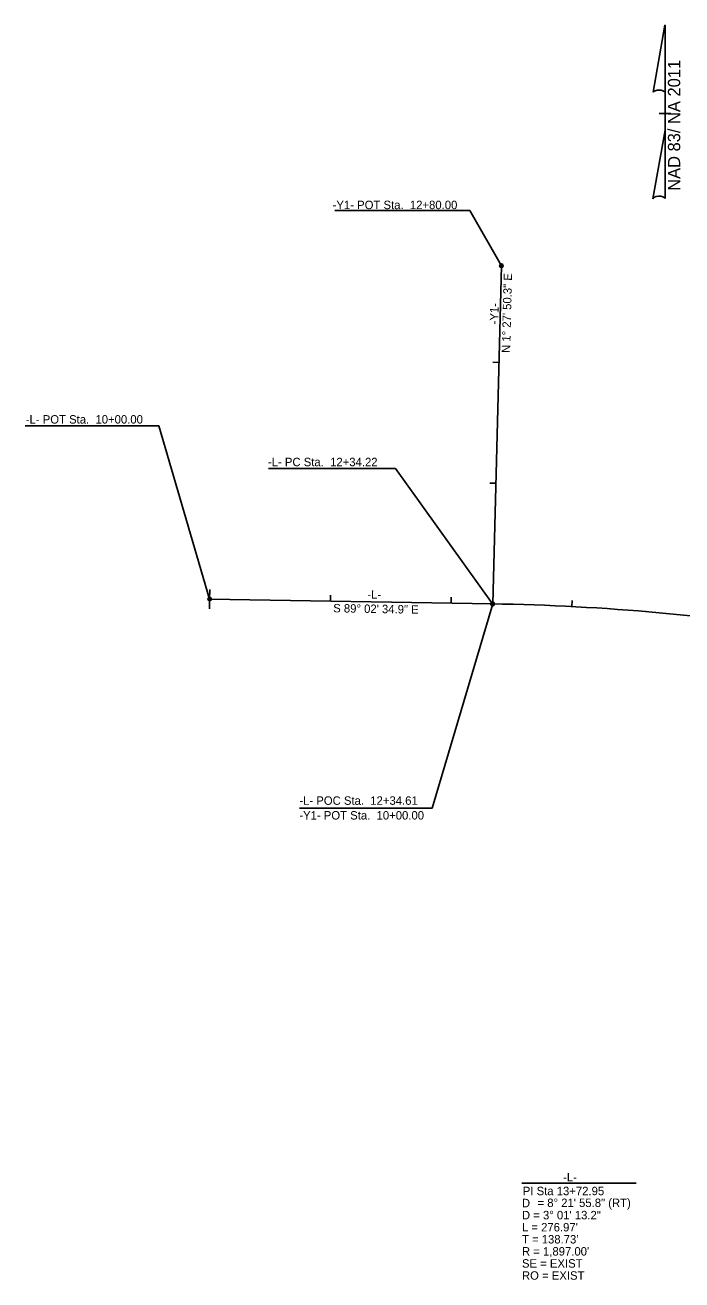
# Model space of a CAD drawing. Extents: x 1755545 to 1761252, y 736169 to 737766.
# Drawn here: x 1755545 to 1756089, y 736596 to 737635 of the extents above; entities that cross this region are included whole.
import ezdxf

# ---------------------------------------------------------------- set-up
doc = ezdxf.new("R2010")
doc.units = 0
for name, color, linetype in [('Prop Horizontal Alignment', 7, 'Continuous'), ('Prop Horizontal Alignment Curve and Spiral Data', 7, 'Continuous'), ('Prop Horizontal Alignment Direction Label', 7, 'Continuous'), ('Prop Horizontal Alignment Station Label', 7, 'Continuous'), ('Prop Horizontal Alignment Tick Large', 7, 'Continuous'), ('Prop Horizontal Alignment Tick Small', 7, 'Continuous'), ('Prop North Arrow NAD83 for Plan Sheets CELL', 7, 'Continuous')]:
    doc.layers.add(name, color=color, linetype=linetype)

msp = doc.modelspace()

# ---------------------------------------------------------------- linework, layer by layer
at = {"layer": 'Prop Horizontal Alignment'}
for p, q in [((1755932.6, 737155.4), (1755939.7, 737435.4)), ((1755698, 737159.4), (1755932.2, 737155.5))]:
    msp.add_line(p, q, dxfattribs=at)
msp.add_arc((1755900.5, 735258.7), 1897, 80.6775, 89.043, dxfattribs=at)
at = {"layer": 'Prop Horizontal Alignment Curve and Spiral Data'}
msp.add_line((1755956.5, 736675.7), (1756051.4, 736675.7), dxfattribs=at)
at = {"layer": 'Prop Horizontal Alignment Station Label'}
for p, q in [((1755801.6, 737481.2), (1755913.5, 737481.2)), ((1755939.7, 737435.4), (1755913.5, 737481.2)), ((1755545.1, 737302.8), (1755655.8, 737302.8)), ((1755698, 737159.4), (1755655.8, 737302.8)), ((1755746.8, 737267.5), (1755851.9, 737267.5)), ((1755932.2, 737155.5), (1755851.9, 737267.5)), ((1755932.6, 737155.4), (1755882.4, 736986.1)), ((1755772.3, 736986.1), (1755882.4, 736986.1))]:
    msp.add_line(p, q, dxfattribs=at)
for centre in [(1755939.7, 737435.4), (1755698, 737159.4), (1755932.2, 737155.5), (1755932.6, 737155.4)]:
    msp.add_circle(centre, 1.5, dxfattribs=at)
at = {"layer": 'Prop Horizontal Alignment Tick Large'}
for p, q in [((1755698, 737159.4), (1755698.1, 737167.4)), ((1755698, 737159.4), (1755697.8, 737151.4)), ((1755932.6, 737155.4), (1755924.6, 737155.7)), ((1755932.6, 737155.4), (1755940.6, 737155.2))]:
    msp.add_line(p, q, dxfattribs=at)
at = {"layer": 'Prop Horizontal Alignment Tick Small'}
for p, q in [((1755937.7, 737355.4), (1755932.7, 737355.5)), ((1755935.1, 737255.4), (1755930.1, 737255.5)), ((1755798, 737157.7), (1755798, 737162.7)), ((1755898, 737156), (1755898, 737161)), ((1755997.9, 737153.2), (1755998.2, 737158.2))]:
    msp.add_line(p, q, dxfattribs=at)
at = {"layer": 'Prop North Arrow NAD83 for Plan Sheets CELL'}
for p, q in [((1756065.3, 737579.1), (1756075.1, 737634.7)), ((1756075.2, 737634.7), (1756075.1, 737634.7)), ((1756075.2, 737634.7), (1756075.1, 737634.7)), ((1756075.2, 737634.7), (1756075.2, 737577.4)), ((1756075.2, 737547.6), (1756075.2, 737579)), ((1756075.2, 737577.4), (1756075.2, 737579)), ((1756070.4, 737561.5), (1756070.3, 737561.5)), ((1756074.7, 737561.5), (1756070.4, 737561.5)), ((1756070.5, 737561.5), (1756080.1, 737561.5)), ((1756075.2, 737547.6), (1756065.2, 737490.9)), ((1756075.3, 737491.1), (1756075.2, 737547.6))]:
    msp.add_line(p, q, dxfattribs=at)
for centre, start_param, end_param in [((1756070.3, 737578.5), 0.216388, 2.908219), ((1756070.3, 737490.7), 0.201328, 3.141593)]:
    msp.add_ellipse(centre, major_axis=(5.08, -0.04), ratio=0.461098, start_param=start_param, end_param=end_param, dxfattribs=at)

# ---------------------------------------------------------------- texts
at = {"layer": 'Prop Horizontal Alignment Curve and Spiral Data'}
for s, p in [('-L-', (1755990.8, 736677.2)), ('PI Sta 13+72.95', (1755957.4, 736665.7)), ('D', (1755956.7, 736655.7)), ('= 8%%d 21\' 55.8" (RT)', (1755969.6, 736655.9)), ('D = 3%%d 01\' 13.2"', (1755956.7, 736645.7)), ("L = 276.97'", (1755956.7, 736635.7)), ("T = 138.73'", (1755956.7, 736625.7)), ("R = 1,897.00'", (1755956.7, 736615.7)), ('SE = EXIST', (1755956.7, 736605.7)), ('RO = EXIST', (1755956.7, 736595.7))]:
    msp.add_text(s, height=7, dxfattribs=at).set_placement(p)
at = {"layer": 'Prop Horizontal Alignment Direction Label'}
for s, rotation, p in [('N 1%%d 27\' 50.3" E', 88.536, (1755946.9, 737363.1)), ('-Y1-', 88.536, (1755937, 737386.8)), ('-L-', 359.043, (1755828.6, 737159.8)), ('S 89%%d 02\' 34.9" E', 359.043, (1755800.3, 737148.4))]:
    msp.add_text(s, height=7, rotation=rotation, dxfattribs=at).set_placement(p)
at = {"layer": 'Prop Horizontal Alignment Station Label'}
for s, p in [('-Y1- POT Sta.  12+80.00', (1755799.9, 737482.3)), ('-L- POT Sta.  10+00.00', (1755545.7, 737304.7)), ('-L- PC Sta.  12+34.22', (1755746.3, 737269.4))]:
    msp.add_text(s, height=7, rotation=360, dxfattribs=at).set_placement(p)
for s, p in [('-L- POC Sta.  12+34.61', (1755772.3, 736989)), ('-Y1- POT Sta.  10+00.00', (1755772.3, 736976.8))]:
    msp.add_text(s, height=7, dxfattribs=at).set_placement(p)
at = {"layer": 'Prop North Arrow NAD83 for Plan Sheets CELL'}
msp.add_text('NAD 83/ NA 2011', height=10.2, rotation=90, dxfattribs=at).set_placement((1756087.8, 737497.5))

doc.saveas('drawing.dxf')
